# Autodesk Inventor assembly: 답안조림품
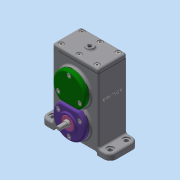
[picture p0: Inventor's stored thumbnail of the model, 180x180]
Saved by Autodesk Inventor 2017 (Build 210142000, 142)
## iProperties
Part Number: 답안조림품
Material: 일반
Document SubType Name: Assembly
Designer: mrc
Author: mrc
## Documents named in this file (24)
- C:\Users\mrc\Desktop\600506V1034\답안조림품.iam
- C:\Users\mrc\Desktop\600506V1034\본체.ipt
- C:\Users\mrc\Desktop\600506V1034\개스킷 A.ipt
- C:\Users\mrc\Desktop\600506V1034\개스킷 B.ipt
- C:\Users\mrc\Desktop\600506V1034\개스킷 C.ipt
- C:\Users\mrc\Desktop\600506V1034\베어링 6001.ipt
- 베어링 6001.ipt
- C:\Users\mrc\Desktop\600506V1034\베어링 6002.ipt
- 베어링 6002.ipt
- C:\Users\mrc\Desktop\600506V1034\볼트 M4.ipt
- C:\Users\mrc\Desktop\600506V1034\스퍼기어 A.ipt
- C:\Users\mrc\Desktop\600506V1034\스퍼기어 B.ipt
- C:\Users\mrc\Desktop\600506V1034\오일 실 10 20 7.ipt
- C:\Users\mrc\Desktop\600506V1034\오일 실 12 22 7.ipt
- C:\Users\mrc\Desktop\600506V1034\축 A.ipt
- C:\Users\mrc\Desktop\600506V1034\축 B.ipt
- C:\Users\mrc\Desktop\600506V1034\칼라.ipt
- C:\Users\mrc\Desktop\600506V1034\커버 A.ipt
- C:\Users\mrc\Desktop\600506V1034\커버 B.ipt
- C:\Users\mrc\Desktop\600506V1034\커버 C.ipt
- C:\Users\mrc\Desktop\600506V1034\커버 D.ipt
- C:\Users\mrc\Desktop\600506V1034\커버 E.ipt
- C:\Users\mrc\Desktop\600506V1034\키 4 x 4 x 12.ipt
- C:\Users\mrc\Desktop\600506V1034\키 5 x 5 x 12.ipt
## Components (5 placed, 3 different names)
1. 개스킷 A:1
2. 개스킷 B:1
3. 개스킷 C:1
4. 개스킷 B:2
5. 개스킷 B:3
